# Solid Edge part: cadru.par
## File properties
Author: Ionut
Template: normal.par
Last saved by: Ionut
Revision: 8
Application: Solid Edge
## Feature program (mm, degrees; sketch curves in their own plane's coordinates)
sketch for "unnamed Protrusion 1" plane through (0, 0, 0) normal (1, 0, 0) x-axis (0, 1, 0)
  circle centre (0, 0) radius 5
extrude "unnamed Protrusion 1" add finite 80 symmetric
sketch for "unnamed Protrusion 2" plane through (40, 0, 0) normal (1, 0, 0) x-axis (0, 1, 0)
  line (-6, -6) -> (6, -6)
  line (6, -6) -> (6, 6)
  line (6, 6) -> (-6, 6)
  line (-6, 6) -> (-6, -6)
extrude "unnamed Protrusion 2" add finite 12 along +normal
sketch for "unnamed Protrusion 3" plane through (46, 0, 6) normal (0, 0, 1) x-axis (1, 0, 0)
  circle centre (0, 0) radius 5
extrude "unnamed Protrusion 3" add finite 80 along +normal
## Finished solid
Body 1: solid body, 10 faces, 16 edges, 8 vertices.
  Faces by surface: plane 8, cylinder 2
  Edges by curve: line 12, circle 4
Bounding box of the edges (mm): 92.000 x 12.000 x 92.000, from (-40, -6, -6) to (52, 6, 86).
Cylindrical faces by radius (mm): R5 x2
Planar faces by outward normal: +x 1, +y 1, +z 2, -x 2, -y 1, -z 1
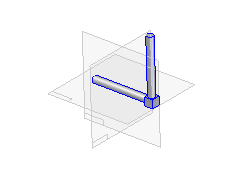
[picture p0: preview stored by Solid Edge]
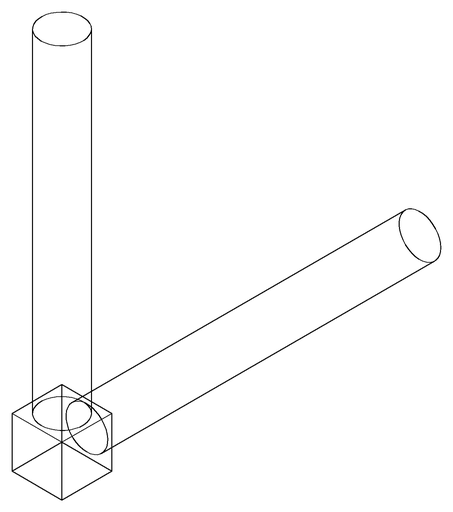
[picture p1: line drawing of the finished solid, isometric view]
